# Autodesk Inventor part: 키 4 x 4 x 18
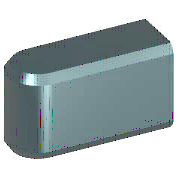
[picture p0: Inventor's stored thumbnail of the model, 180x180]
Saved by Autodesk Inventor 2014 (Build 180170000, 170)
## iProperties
IsCustomPart: 1
Created: 2012-02
Part Number: 키 4 x 4 x 18
Material: 강철, 연강
Description: 키 및 해당 키홈
Document SubType Name: Modeling
Standard: KS B 1311
Designer: mduedu
Standards Organization: KS
Language: ko-KR
Size Designation: 4 x 4 x 18
Categories: <MemberInstance><Categories><Category DisplayName="샤프트 부품" InternalName="7f7aeb1f-a693-4053-b835-cee3144e0d98" Mnemonic="SHFT"><Category DisplayName="키" Interna
Density: 1 g/cm^3
Appearance: 주황색
Author: mduedu
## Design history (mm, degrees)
sketch "스케치1"
  geometry: L1 (2, 2)-(18, 2); L2 (18, 2)-(18, -2); L3 (18, -2)-(2, -2); L4 (0, 7)-(0, -7) reference; L5 (-5, 0)-(30, 0) reference; A1 r 2 centre (2, 0) between (2, 2) and (2, -2)
  constraints: 6 end point, 3 tangent, 2 point on circle, 1 centre point, 1 horizontal, 1 parallel, 1 perpendicular, 1 point on line
  dimensions: "d0" = 2 radius of A1 (= 0.5 x PB); "d7" = 18 distance between parallel lines of L2 L4 (= NLG)
workplane "Work Plane1"
workplane "Work Plane2"
extrude "본체1" new body sketch "스케치1" taper "d3" = 0 deg; stored distance "d4" = 10
workaxis "Work Axis1"
workplane "Work Plane4"
body "Solid1"
chamfer "모따기1" distance "d8" = 0.25 (= PHH); stored, may be unused: second distance "d9" = 0.25 (= PHH), angle "d13" = 45 deg
other parameters: "d1" = -2.5 (= -PNT), "d2" = 1.5 (= PH - PNT), "NLG" = 18 [user parameter; used in 2 equation terms], "PB" = 4 [user parameter; used in 1 equation term], "PNT" = 2.5 [user parameter; used in 2 equation terms], "PH" = 4 [user parameter; used in 1 equation term], "PHH" = 0.25 [user parameter; used in 2 equation terms], "d10" = 0, "d16" = 0, "d17" = 0, "d18" = 0, "RR" = 0.08 [user parameter], "WDMAX" = 12 [user parameter], "PLB1" = 18 (= NLG) [user parameter], "PUEB" = 1.8 [user parameter]
